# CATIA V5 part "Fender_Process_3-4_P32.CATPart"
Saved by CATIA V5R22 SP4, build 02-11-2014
Part number: Fender
Bounding box of the stored display mesh (mm): x -800 to 0, y -40 to 122.298, z 0 to 580
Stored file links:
  C:\DATA\Car_ASSY\教育モデル\3_SOL\Fender_Process_3-4_P33.CATPart
  C:\DATA\Car_ASSY\教育モデル\3_SOL\Car_Fender.CATPart
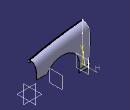
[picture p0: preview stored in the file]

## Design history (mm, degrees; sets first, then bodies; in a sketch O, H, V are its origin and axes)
Set1
  Plane1: type Offset, RefPlane yz-plane, Offset 400, reversed
  Plane2: type Offset, RefPlane Plane1, Offset 400, reversed
Body1 (main body)
Body2
  Sketch1 on yz-plane, origin (0, 0, 0), H (0, 1, 0), V (0, 0, 1)
    point P4 (100, 50)
    point P5 (10, 450)
    spline S1 through (10, 450) (100, 50)
    line L1 (0, 450) -> (10, 450)
    line L2 (0, 0) -> (0, 450)
    line L3 (100, 0) -> (0, 0)
    line L4 (100, 50) -> (100, 0)
    point P6 (100, 50)
    point P7 (10, 450)
    distance P4 L3 = 50
    distance P5 L2 = 10
    distance L4 L2 = 100
    distance L1 H = 450
    coincidence: L2 V, H L3, P4 P6, P7 P5
  Sketch2 on Plane1, origin (-400, 0, 0), H (0, 1, 0), V (0, 0, 1)
    point P4 (100, 50)
    point P5 (10, 530)
    spline S1 through (10, 530) (100, 50)
    line L1 (0, 530) -> (10, 530)
    line L2 (0, 0) -> (0, 530)
    line L3 (100, 0) -> (0, 0)
    line L4 (100, 50) -> (100, 0)
    point P6 (100, 50)
    point P7 (10, 530)
    distance P4 L3 = 50
    distance P5 L2 = 10
    distance L4 L2 = 100
    distance L1 H = 530
    coincidence: L2 V, H L3, P4 P6, P7 P5
  Sketch3 on Plane2, origin (-800, 0, 0), H (0, 1, 0), V (0, 0, 1)
    point P4 (100, 50)
    point P5 (10, 580)
    spline S1 through (10, 580) (100, 50)
    line L1 (0, 580) -> (10, 580)
    line L2 (0, 0) -> (0, 580)
    line L3 (100, 0) -> (0, 0)
    line L4 (100, 50) -> (100, 0)
    point P6 (100, 50)
    point P7 (10, 580)
    distance P4 L3 = 50
    distance P5 L2 = 10
    distance L4 L2 = 100
    distance L1 H = 580
    coincidence: L2 V, H L3, P4 P6, P7 P5
  Loft1: solid, Sections (Sketch1; Sketch2; Sketch3)
  Body3
    Sketch4 on zx-plane, origin (0, 0, 0), H (-1, 0, 0), V (0, 0, 1)
      line L1 (-46.4952, 240) -> (159.0779, 240)
      arc A1 centre (390, 110) radius 265 from (159.0779, 240) to (655, 109.9999) cw
      point P2 (390, 110)
      line L2 (655, 109.9999) -> (655, -30)
      line L3 (-46.4952, 626.6258) -> (850, 626.6258)
      line L4 (850, 626.6258) -> (850, -30)
      line L5 (850, -30) -> (655, -30)
      line L6 (-46.4952, 626.6258) -> (-46.4952, 240)
      radius A1 = 265
      distance P2 H = 110
      distance V P2 = 390
      distance H L1 = 240
      horizontal: L1 H, L3 H, L5 H
      tangency: L2 A1
      vertical: L2 V, L4 V, L6 V
    Pad1: profile Sketch4, direction (0, 1, 0), length 340, mirrored extent
  Intersect1: tool Body3
  Shell1: ExtOffset 0, Face (face of Loft1; face of Loft1; face of Pad1 from Sketch4.A1; face of Pad1 from Sketch4.L1; face of Loft1; face of Loft1), IntOffset 3
  Sketch5 on Plane2, origin (-800, 0, 0), H (0, 1, 0), V (0, 0, 1)
    line L1 (0, 580) -> (0, 545)
    line L2 (-5, 540) -> (-40, 540)
    point P2 (-40, 540)
    reference projected line E1 (10, 580) -> (0, 580)
    reference intersected line E2 (0, 0) -> (0, 580)
    arc A1 centre (-5, 545) radius 5 from (-5, 540) to (0, 545) ccw
    line L3 (-5, 537) -> (-40, 537)
    arc A2 centre (-5, 545) radius 8 from (-5, 537) to (3, 545) ccw
    line L4 (3, 580) -> (3, 545)
    line L5 (-40, 537) -> (-40, 540)
    line L6 (3, 580) -> (0, 580)
    reference projected line E3 (10, 580) -> (0, 580)
    distance E1 L2 = 40
    radius A1 = 5
    distance L1 P2 = 40
    length L5 = 3
    length L6 = 3
    radius A2 = 8
    vertical: L1 V, L4 V, L5 V
    horizontal: L2 H, L6 H, L3 H
    coincidence: L1 E2, L6 E3
    tangency: A1 L2, A1 L1, L4 A2, A2 L3
  Rib1: profile Sketch5, centre curve edge [face of Loft1 | face of Loft1]
  Sketch6 on Plane2, origin (-800, 0, 0), H (0, 1, 0), V (0, 0, 1)
    projected curve E1
    projected line E2 (10, 576.9862) -> (3, 576.9862)
    point P4 (3, 576.9862)
    projected line E3 (3, 576.9862) -> (3, 545)
    projected line E4 (3, 576.9862) -> (3, 399.233)
    point P5 (3, 576.9862)
    projected line E5 (97, 0) -> (97, 50)
    line L1 (97, 0) -> (37, 0)
    line L2 (37, 0) -> (17.9077, 155.4943)
    arc A1 centre (2003, 399.233) radius 2000 from (3, 399.233) to (17.9077, 155.4943) ccw
    angle L1 L2 = 97
    length L1 = 60
    radius A1 = 2000
    horizontal: L1 H
    tangency: A1 E3, A1 L2
    coincidence: P4 P5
